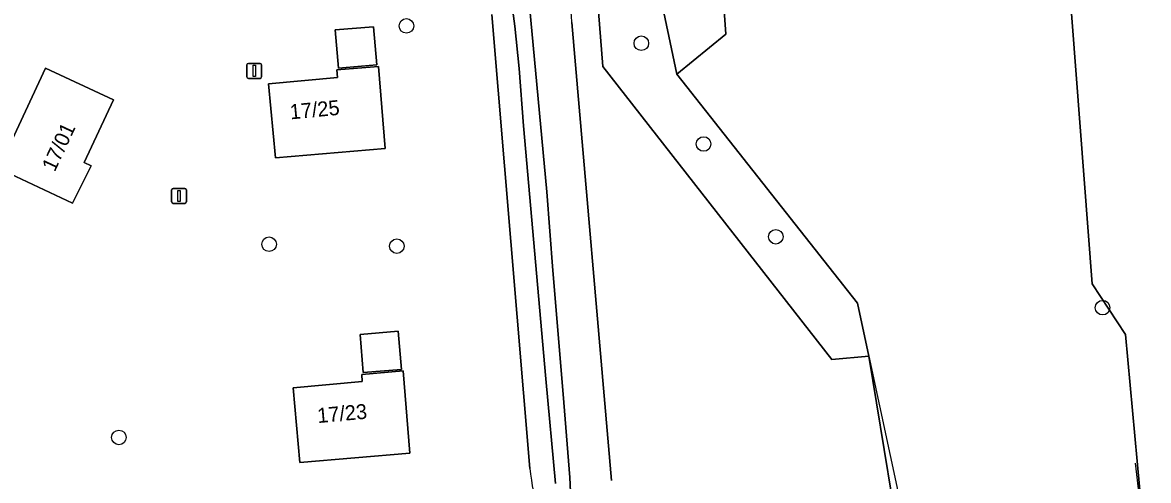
# Model space of a CAD drawing. Extents: x 157793 to 159380, y 380877 to 382313.
# Drawn here: x 157981 to 158056.4, y 381170.1 to 381200.7 of the extents above; entities that cross this region are included whole.
import ezdxf

# ---------------------------------------------------------------- set-up
doc = ezdxf.new("R2010")
doc.units = 0
for name, color, linetype in [('IMGEO_Boom', 7, 'Continuous'), ('IMGEO_Erf', 7, 'Continuous'), ('IMGEO_Groenvoorziening', 7, 'Continuous'), ('IMGEO_Hek', 7, 'Continuous'), ('IMGEO_Lichtmast', 7, 'Continuous'), ('IMGEO_Loofbos', 7, 'Continuous'), ('IMGEO_Oever', 7, 'Continuous'), ('IMGEO_Pand', 7, 'Continuous'), ('IMGEO_Pand_nummerreeks', 7, 'Continuous'), ('IMGEO_Waterloop', 7, 'Continuous')]:
    doc.layers.add(name, color=color, linetype=linetype)

msp = doc.modelspace()

# ---------------------------------------------------------------- linework, layer by layer
at = {"layer": 'IMGEO_Boom'}
for centre in [(158006.705, 381200.522), (158022.451, 381199.359), (158026.622, 381192.608), (157997.504, 381185.893), (158006.064, 381185.761), (158031.468, 381186.388), (158053.367, 381181.639), (157987.433, 381172.944)]:
    msp.add_circle(centre, 0.489, dxfattribs=at)
at = {"layer": 'IMGEO_Erf'}
msp.add_lwpolyline([(158099.611, 381217.247), (158052.783, 381213.5), (158050.314, 381213.946), (158050.517, 381211.312), (158052.682, 381183.227), (158054.909, 381179.836), (158056.161, 381166.26), (158053.899, 381166.074), (158054.334, 381160.498), (158058.211, 381110.918)], dxfattribs=at)
at = {"layer": 'IMGEO_Groenvoorziening'}
for points in [[(158058.211, 381110.918), (158054.334, 381160.498), (158053.899, 381166.074), (158056.161, 381166.26), (158054.909, 381179.836), (158052.682, 381183.227), (158050.517, 381211.312), (158039.034, 381210.37), (158038.773, 381213.455), (158034.585, 381213.111), (158034.869, 381210.038), (158027.452, 381209.42), (158028.11, 381199.967), (158024.833, 381197.293), (158036.947, 381181.933), (158037.709, 381178.388), (158039.767, 381165.888), (158046.317, 381163.549), (158054.886, 381034.528), (158055.954, 381019.408), (158065.175, 380995.891)], [(158065.175, 380995.891), (158055.954, 381019.408), (158054.886, 381034.528), (158046.317, 381163.549), (158039.767, 381165.888), (158037.709, 381178.388), (158035.215, 381178.178), (158019.881, 381197.791), (158019.23, 381206.041), (158018.738, 381212.267), (158021.715, 381212.507), (158027.429, 381212.967)], [(158014.988, 381170.868), (158012.439, 381201.273)], [(158017.804, 381200.746), (158020.445, 381170.062)]]:
    msp.add_lwpolyline(points, dxfattribs=at)
for points in [[(158022.372, 381208.957), (158024.833, 381197.293), (158028.11, 381199.967), (158027.452, 381209.42)], [(158002.158, 381197.697), (158001.941, 381200.253), (158004.5, 381200.466), (158004.714, 381197.91)], [(157985.099, 381191.358), (157985.576, 381191.133), (157984.327, 381188.644), (157979.362, 381190.966), (157982.51, 381197.696), (157987.066, 381195.565)], [(157997.926, 381191.684), (157997.464, 381196.628), (158002.095, 381197.062), (158002.048, 381197.567), (158004.828, 381197.799), (158005.287, 381192.298)], [(158003.603, 381179.846), (158006.158, 381180.062), (158006.374, 381177.506), (158003.818, 381177.29)], [(158003.748, 381176.685), (158003.713, 381177.166), (158006.478, 381177.399), (158006.942, 381171.899), (157999.57, 381171.276), (157999.119, 381176.267)]]:
    msp.add_lwpolyline(points, close=True, dxfattribs=at)
for centre, radius, start, end in [((157994.663, 381199.39), 23.181, 3.35248, 37.9619), ((158032.528, 381172.642), 17.629, 185.77405, 206.15711)]:
    msp.add_arc(centre, radius, start, end, dxfattribs=at)
at = {"layer": 'IMGEO_Hek'}
for points in [[(158027.452, 381209.42), (158022.372, 381208.957), (158024.833, 381197.293)], [(158037.709, 381178.388), (158040.568, 381165.078), (158053.899, 381166.074)], [(158056.161, 381166.26), (158055.587, 381171.227)]]:
    msp.add_lwpolyline(points, dxfattribs=at)
at = {"layer": 'IMGEO_Lichtmast'}
for p, q in [((157996.012, 381197.104), (157996.012, 381197.904)), ((157996.012, 381197.904), (157996.012, 381197.104)), ((157996.112, 381198.004), (157996.902, 381198.004)), ((157996.902, 381198.004), (157996.112, 381198.004)), ((157997.002, 381197.904), (157997.002, 381197.104)), ((157997.002, 381197.104), (157997.002, 381197.904)), ((157996.902, 381197.004), (157996.112, 381197.004)), ((157996.112, 381197.004), (157996.902, 381197.004)), ((157990.966, 381188.725), (157990.966, 381189.525)), ((157990.966, 381189.525), (157990.966, 381188.725)), ((157991.066, 381189.625), (157991.856, 381189.625)), ((157991.856, 381189.625), (157991.066, 381189.625)), ((157991.956, 381189.525), (157991.956, 381188.725)), ((157991.956, 381188.725), (157991.956, 381189.525)), ((157991.856, 381188.625), (157991.066, 381188.625)), ((157991.066, 381188.625), (157991.856, 381188.625))]:
    msp.add_line(p, q, dxfattribs=at)
for points in [[(157996.432, 381197.879), (157996.582, 381197.879), (157996.582, 381197.129), (157996.432, 381197.129), (157996.432, 381197.879)], [(157991.386, 381189.5), (157991.536, 381189.5), (157991.536, 381188.75), (157991.386, 381188.75), (157991.386, 381189.5)]]:
    msp.add_lwpolyline(points, dxfattribs=at)
for centre, start, end in [((157996.112, 381197.904), 90, 180), ((157996.112, 381197.904), 90, 180), ((157996.902, 381197.904), 0, 90), ((157996.902, 381197.904), 360, 90), ((157996.112, 381197.104), 180, 270), ((157996.112, 381197.104), 180, 270), ((157996.902, 381197.104), 270, 0), ((157996.902, 381197.104), 270, 0), ((157991.066, 381189.525), 90, 180), ((157991.066, 381189.525), 90, 180), ((157991.856, 381189.525), 0, 90), ((157991.856, 381189.525), 360, 90), ((157991.066, 381188.725), 180, 270), ((157991.066, 381188.725), 180, 270), ((157991.856, 381188.725), 270, 0), ((157991.856, 381188.725), 270, 0)]:
    msp.add_arc(centre, 0.1, start, end, dxfattribs=at)
at = {"layer": 'IMGEO_Loofbos'}
msp.add_lwpolyline([(158037.709, 381178.388), (158036.947, 381181.933), (158024.833, 381197.293), (158022.372, 381208.957), (158021.715, 381212.507), (158018.738, 381212.267), (158019.23, 381206.041), (158019.881, 381197.791), (158035.215, 381178.178)], close=True, dxfattribs=at)
at = {"layer": 'IMGEO_Oever'}
for points in [[(158014.549, 381193.816), (158014.258, 381197.663), (158013.964, 381200.509), (158013.525, 381203.859)], [(158014.954, 381201.869), (158016.119, 381189.401), (158016.512, 381184.138), (158017.205, 381175.847), (158017.65, 381170.266), (158017.734, 381168.814)], [(158012.439, 381201.273), (158014.988, 381170.868)], [(158020.445, 381170.062), (158017.804, 381200.746)], [(158016.705, 381169.852), (158016.044, 381176.875), (158014.549, 381193.816)]]:
    msp.add_lwpolyline(points, dxfattribs=at)
for centre, radius, start, end in [((157994.663, 381199.39), 23.181, 3.35248, 37.9619), ((158032.528, 381172.642), 17.629, 185.77405, 206.15711)]:
    msp.add_arc(centre, radius, start, end, dxfattribs=at)
at = {"layer": 'IMGEO_Pand'}
for points in [[(158004.714, 381197.91), (158004.5, 381200.466), (158001.941, 381200.253), (158002.158, 381197.697)], [(157987.066, 381195.565), (157982.51, 381197.696), (157979.362, 381190.966), (157984.327, 381188.644), (157985.576, 381191.133), (157985.099, 381191.358)], [(158004.828, 381197.799), (158002.048, 381197.567), (158002.095, 381197.062), (157997.464, 381196.628), (157997.926, 381191.684), (158005.287, 381192.298)], [(158003.818, 381177.29), (158006.374, 381177.506), (158006.158, 381180.062), (158003.603, 381179.846)], [(158006.478, 381177.399), (158003.713, 381177.166), (158003.748, 381176.685), (157999.119, 381176.267), (157999.57, 381171.276), (158006.942, 381171.899)]]:
    msp.add_lwpolyline(points, close=True, dxfattribs=at)
at = {"layer": 'IMGEO_Waterloop'}
for points in [[(158013.525, 381203.859), (158013.964, 381200.509), (158014.258, 381197.663), (158014.549, 381193.816), (158016.044, 381176.875), (158016.705, 381169.852)], [(158017.734, 381168.814), (158017.65, 381170.266), (158017.205, 381175.847), (158016.512, 381184.138), (158016.119, 381189.401), (158014.954, 381201.869)]]:
    msp.add_lwpolyline(points, dxfattribs=at)

# ---------------------------------------------------------------- texts
at = {"layer": 'IMGEO_Pand_nummerreeks'}
for s, rotation, p in [('17/25', 5.35143, (157998.934, 381194.255)), ('17/01', 64.93904, (157983.132, 381190.691)), ('17/23', 5.16235, (158000.775, 381173.906))]:
    msp.add_text(s, height=1, rotation=rotation, dxfattribs=at).set_placement(p)

doc.saveas('drawing.dxf')
